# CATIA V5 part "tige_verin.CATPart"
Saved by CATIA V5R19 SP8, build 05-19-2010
Part number: tige_verin
Bounding box of the stored display mesh (mm): x -110 to 110, y -187.811 to 1605, z -109.814 to 109.814
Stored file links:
  C:\Users\ThinkMotion\Desktop\EU_thinkMotion\iao\IAO_MMS_Groupe3\gdespas\projet_Thinkmotion_GDESPAS\projet Thinkmotion GDESPAS\Assemblage gdespas\tige_verin.CATPart
  C:\Users\ThinkMotion\Desktop\EU_thinkMotion\iao\IAO_MMS_Groupe3\gdespas\projet_Thinkmotion_GDESPAS\projet Thinkmotion GDESPAS\Assemblage gdespas\corps_verin.CATPart
  C:\Users\ThinkMotion\Desktop\EU_thinkMotion\iao\IAO_MMS_Groupe3\gdespas\projet_Thinkmotion_GDESPAS\projet Thinkmotion GDESPAS\Assemblage gdespas\Assemblage IAO.CATProduct
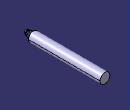
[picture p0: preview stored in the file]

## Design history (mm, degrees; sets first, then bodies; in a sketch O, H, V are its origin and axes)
External parameters (linked from other documents)
  External.diam_axe = 0.126
Body1 (main body)
  Sketch1 on zx-plane, origin (0, 0, 0), H (-1, 0, 0), V (0, 0, 1)
    circle A1 centre (0, 0) radius 110
    radius A1 = 110
  Pad1: profile Sketch1, direction (0, 1, 0), length 1605
  Sketch2 on yz-plane, origin (0, 0, 0), H (0, 1, 0), V (0, 0, 1)
    line L1 (0, 100) -> (0, -100)
    point P1 (0, 100)
    point P2 (0, -100)
    reference projected line E1 through (0, 0) direction (1, 0) from axis of face of Pad1 from Sketch1.A1
    reference projected line E2 (0, 110) -> (0, -110) from edge [start face of Pad1 | face of Pad1 from Sketch1.A1]
    circle A1 centre (-100, 0) radius 63
    point P3 (-100, 0)
    line L2 (0, -100) -> (-140.3028, -64.8983)
    point P4 (-140.3028, -64.8983)
    reference intersected line E3 through (0, 0) direction (-1, 0) from xy-plane
    point P7 (-140.3028, 64.8983)
    point P8 (0, 100)
    line L3 (0, 100) -> (-140.3028, 64.8983)
    arc A2 centre (-120, 0) radius 68 from (-140.3028, 64.8983) to (-140.3028, -64.8983) ccw
    point P9 (-120, 0)
    point P10 (-188, 0)
    reference projected line E4 (0, 110) -> (0, -110) from edge [start face of Pad1 | face of Pad1 from Sketch1.A1]
    reference projected line E5 (0, 110) -> (0, -110) from edge [start face of Pad1 | face of Pad1 from Sketch1.A1]
    length L1 = 200
    radius A1 = 63 {= External.diam_axe /2}
    radius A2 = 68
    distance E4 P3 = 100
    distance P9 E5 = 120
    length L2 = 144.6272
    perpendicularity: L1 E1
    coincidence: E2 L1, P3 H, A2 P10, P10 E3, P1 P8
    symmetry: P4 P7 E3, P2 P8 E3, L2 L3 E3
  Pad2: profile Sketch2, direction (1, 0, 0), length 10, opposite side length 10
